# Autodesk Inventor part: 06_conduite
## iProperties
Shininess: 20.0
Length Units: 11269
Angle Units: 11279
Time Units: 11290
Mass Units: 11283
Length Display Precision: 3
Angle Display Precision: 2
Compacted: True
Created: 2002-11
Part Number: 06_conduite
Material: Aluminum-6061
Document SubType Name: Modélisation
Designer: FIEVET
Density: 2.71
Volumn: 4.624440358255763
Area: 35.612312209552115
PropertySet Name: Model Information
Control State: 0
Master: False
Checked Out: False
Author: FIEVET
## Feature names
1. Révolution1 [Revolution]
2. Extrusion1
3. Chanfrein1 [Chamfer]
4. Perçage1 [Hole]
5. Révolution2 [Revolution]
6. Extrusion2
7. Extrusion5
